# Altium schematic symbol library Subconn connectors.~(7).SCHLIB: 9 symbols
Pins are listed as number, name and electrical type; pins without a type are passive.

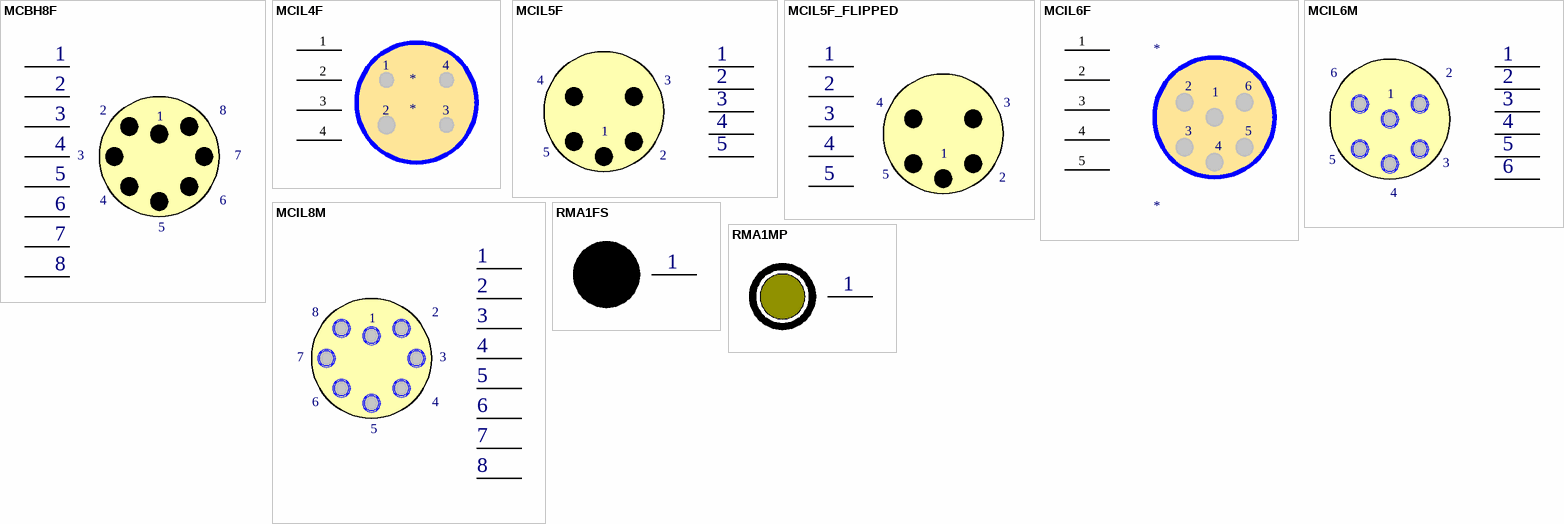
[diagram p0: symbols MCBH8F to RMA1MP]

## MCBH8F
designator *
Subconn MCBH8F bulkhead connector
pins: 1, 2, 3, 4, 5, 6, 7, 8

## MCIL4F
designator *
pins: 1, 2, 3, 4

## MCIL5F
designator *  (value not drawn)
Subconn MCIL5F pigtail
pins: 1, 2, 3, 4, 5

## MCIL5F_FLIPPED
designator *, comment MCIL5F_flip  (value not drawn)
Subconn MCIL5F pigtail
pins: 1, 2, 3, 4, 5

## MCIL6F
designator *
pins: 1, 2, 3, 4, 5

## MCIL6M
designator *  (value not drawn)
Subconn MCIL6M pigtail
pins: 1, 2, 3, 4, 5, 6

## MCIL8M
designator *
Subconn MCIL8M pigtail
pins: 1, 2, 3, 4, 5, 6, 7, 8

## RMA1FS
designator *, comment RMA-1-FS  (value not drawn)
Impulse RMA-1-FS pigtail
pins: 1

## RMA1MP
designator *, comment RMA-1-MP  (value not drawn)
Impulse RMA-1-MP pigtail
pins: 1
